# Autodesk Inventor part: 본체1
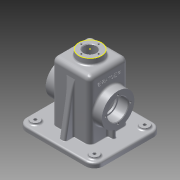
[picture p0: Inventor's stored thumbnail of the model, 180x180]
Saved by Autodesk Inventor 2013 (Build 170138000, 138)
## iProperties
Created: 2016-01
Part Number: 본체1
Material: 알루미늄 6061
Document SubType Name: Modeling
Designer: Administrator
Density: 2.71 g/cm^3
Mass: 805.054 g
Surface Area: 908.341 cm^2
Volume: 297.068 cm^3
Author: Administrator
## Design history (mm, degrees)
sketch "스케치1"
  geometry: 1 further point
sketch "스케치2"
  geometry: L1 (-32.5, 32.5)-(32.5, 32.5); L2 (32.5, 32.5)-(32.5, -32.5); L3 (32.5, -32.5)-(-32.5, -32.5); L4 (-32.5, -32.5)-(-32.5, 32.5); 3 further points
  constraints: 8 end point, 2 midpoint, 2 parallel, 1 horizontal, 1 horizontal alignment, 1 perpendicular, 1 vertical alignment
  dimensions: "d0" = 65 distance of L1.start L1.end; "d2" = 65 distance of L1.end L2.end
extrude "돌출1" new body sketch "스케치2" distance "d3" = 110; taper "d4" = 0 deg
fillet "모깎기1" dims "d5" = 8
fillet "모깎기2" dims "d6" = 8
feature "쉘1" dims "d7" = 5
sketch "스케치3"
  geometry: C1 r 20 at (0, 0); 1 further point
  constraints: 1 centre point, 1 coincident
  dimensions: "d8" = 40 diameter of C1
extrude "돌출2" join sketch "스케치3" distance "d9" = 10; taper "d10" = 0 deg
feature "면 기울기1" dims angle "d11" = 5 deg
sketch "스케치4"
  geometry: C1 r 19.125 at (0, 0) reference
hole "구멍1" diameter "d14" = 21; stored, may be unused: countersink angle "d18" = 90 deg, drill point angle "d20" = 0 deg; dims "d12" = 10, "d13" = 10, "d15" = 6, "d16" = 4, "d17" = 2, "d19" = 8
sketch "스케치5"
  geometry: L1 (0, 0)-(0, 49) reference; C1 r 27.5 at (55, 24.5); 3 further points
  constraints: 1 centre point, 1 coincident, 1 horizontal alignment, 1 midpoint
  dimensions: "d21" = 55 distance of point (0, 24.5) point (55, 24.5); "d22" = 55 diameter of C1
extrude "돌출3" join sketch "스케치5" distance "d23" = 15; taper "d25" = 0 deg; dims "d24" = 5, "d26" = 0
hole "구멍2" diameter "d29" = 30; stored, may be unused: countersink angle "d33" = 90 deg, drill point angle "d35" = 0 deg; dims "d27" = 10, "d28" = 10, "d30" = 6, "d31" = 35, "d32" = 17, "d34" = 8
sketch "스케치6"
  geometry: L1 (24.5, 32.5)-(-24.5, 32.5) reference; L2 (-32.5, 24.5)-(-32.5, -24.5) reference; L3 (-24.5, -32.5)-(24.5, -32.5) reference; L4 (32.5, -24.5)-(32.5, 24.5) reference; L5 (-65, -57.5)-(65, -57.5); L6 (65, -57.5)-(65, 57.5); L7 (65, 57.5)-(-65, 57.5); L8 (-65, 57.5)-(-65, -57.5); A1 r 8 centre (24.5, 24.5) between (32.5, 24.5) and (24.5, 32.5) reference; A2 r 8 centre (-24.5, 24.5) between (-24.5, 32.5) and (-32.5, 24.5) reference; A3 r 8 centre (-24.5, -24.5) between (-32.5, -24.5) and (-24.5, -32.5) reference; A4 r 8 centre (24.5, -24.5) between (24.5, -32.5) and (32.5, -24.5) reference; 3 further points
  constraints: 8 end point, 2 midpoint, 2 parallel, 1 horizontal, 1 horizontal alignment, 1 perpendicular, 1 vertical alignment
  dimensions: "d36" = 115 distance of L7.end L5.start; "d38" = 130 distance of L6.end L7.end
extrude "돌출4" join sketch "스케치6" distance "d39" = 10; taper "d40" = 0 deg
fillet "모깎기3" dims "d41" = 15
sketch "스케치7"
  geometry: L1 (50, 57.5)-(-50, 57.5) reference; L2 (-65, 42.5)-(-65, -42.5) reference; L3 (-50, -57.5)-(50, -57.5) reference; L4 (65, -42.5)-(65, 42.5) reference; L5 (50, -52.5)-(-50, -52.5); L6 (-60, -42.5)-(-60, 42.5); L7 (-50, 52.5)-(50, 52.5); L8 (60, 42.5)-(60, -42.5); A1 r 15 centre (50, 42.5) between (65, 42.5) and (50, 57.5) reference; A2 r 15 centre (-50, 42.5) between (-50, 57.5) and (-65, 42.5) reference; A3 r 15 centre (-50, -42.5) between (-65, -42.5) and (-50, -57.5) reference; A4 r 15 centre (50, -42.5) between (50, -57.5) and (65, -42.5) reference; A5 r 10 centre (-50, -42.5) between (-60, -42.5) and (-50, -52.5); A6 r 10 centre (-50, 42.5) between (-50, 52.5) and (-60, 42.5); A7 r 10 centre (50, 42.5) between (60, 42.5) and (50, 52.5); A8 r 10 centre (50, -42.5) between (50, -52.5) and (60, -42.5); 1 further point
  constraints: 8 end point, 8 point on circle, 4 centre point, 7 other
  dimensions: "d42" = 5 distance between parallel lines of L3 L5
extrude "돌출5" cut sketch "스케치7" distance "d43" = 2; taper "d44" = 0 deg
sketch "스케치8"
  geometry: C1 r 17.5 at (0, 0) reference; 2 further points
  constraints: 1 horizontal alignment
  dimensions: "d45" = 21 distance of point (21, 0) C1.centre
hole "구멍3" sketch "스케치8" at (21, 0) diameter "d46" = 3.242; stored, may be unused: countersink angle "d50" = 90 deg, drill point angle "d52" = 118 deg; dims "d47" = 8, "d48" = 35, "d49" = 17, "d51" = 10
sketch "스케치9"
  geometry: C1 r 10.5 at (0, 0) reference; 1 further point
  constraints: 1 horizontal alignment
  dimensions: "d56" = 14.5 distance of C1.centre point (-14.5, 0)
hole "구멍4" sketch "스케치9" at (-14.5, 0) diameter "d57" = 2.459; stored, may be unused: countersink angle "d61" = 90 deg, drill point angle "d63" = 118 deg; dims "d58" = 7, "d59" = 35, "d60" = 17, "d62" = 9
sketch "스케치10"
  geometry: C1 r 7.5 at (-50, -42.5); C2 r 7.5 at (-50, 42.5); C3 r 7.5 at (50, 42.5); C4 r 7.5 at (50, -42.5); A1 r 15 centre (-50, 42.5) between (-50, 57.5) and (-65, 42.5) reference; A2 r 15 centre (-50, -42.5) between (-65, -42.5) and (-50, -57.5) reference; A3 r 15 centre (50, -42.5) between (50, -57.5) and (65, -42.5) reference; A4 r 15 centre (50, 42.5) between (65, 42.5) and (50, 57.5) reference; 1 further point
  constraints: 4 centre point, 4 coincident
  dimensions: "d67" = 15 diameter of C1; "d68" = 15 diameter of C2; "d69" = 15 diameter of C3; "d70" = 15 diameter of C4
extrude "돌출6" join sketch "스케치10" distance "d71" = 3; taper "d72" = 0 deg
hole "구멍5" diameter "d75" = 5; stored, may be unused: countersink angle "d79" = 90 deg, drill point angle "d81" = 118 deg; dims "d73" = 10, "d74" = 10, "d76" = 7, "d77" = 35, "d78" = 17, "d80" = 9
sketch "스케치11"
  geometry: L1 (-47.5, 37.5)-(-30.5, 37.5) reference; L2 (-30.5, 37.5)-(-30.5, 40) reference; L3 (-30.5, 40)-(-27.5, 40) reference; L4 (-27.5, 40)-(-27.5, 0) reference; L5 (-27.5, 0)-(-60, 0) reference; L6 (-60, 0)-(-60, 2) reference; L7 (-60, 2)-(-65, 2) reference; L8 (-65, 2)-(-65, 10) reference; L9 (-65, 10)-(-32.5, 10) reference; L10 (-32.5, 10)-(-32.5, 27.5) reference; L11 (-32.5, 27.5)-(-47.5, 27.5) reference; L12 (-47.5, 27.5)-(-47.5, 32.379) reference; L13 (-47.5, 32.379)-(-37.5, 32.379) reference; L14 (-37.5, 32.379)-(-36.526, 34) reference; L15 (-36.526, 34)-(-37.5, 35.621) reference; L16 (-37.5, 35.621)-(-47.5, 35.621) reference; L17 (-47.5, 35.621)-(-47.5, 37.5) reference; L18 (47.5, 27.5)-(32.5, 27.5) reference; L19 (32.5, 27.5)-(32.5, 10) reference; L20 (32.5, 10)-(65, 10) reference; L21 (65, 10)-(65, 2) reference; L22 (65, 2)-(60, 2) reference; L23 (60, 2)-(60, 0) reference; L24 (60, 0)-(27.5, 0) reference; L25 (27.5, 0)-(27.5, 40) reference; L26 (30.5, 40)-(30.5, 37.5) reference; L27 (30.5, 37.5)-(47.5, 37.5) reference; L28 (47.5, 37.5)-(47.5, 35.621) reference; L29 (47.5, 35.621)-(37.5, 35.621) reference; L30 (37.5, 35.621)-(36.526, 34) reference; L31 (36.526, 34)-(37.5, 32.379) reference; L32 (37.5, 32.379)-(47.5, 32.379) reference; L33 (47.5, 32.379)-(47.5, 27.5) reference; L34 (19.125, 120)-(20, 110) reference; L35 (20, 110)-(24.5, 110) reference; L36 (32.5, 102)-(32.5, 82.5) reference; L37 (32.5, 82.5)-(47.5, 82.5) reference; L38 (47.5, 82.5)-(47.5, 77.621) reference; L39 (47.5, 77.621)-(37.5, 77.621) reference; L40 (37.5, 77.621)-(36.526, 76) reference; L41 (36.526, 76)-(37.5, 74.379) reference; L42 (37.5, 74.379)-(47.5, 74.379) reference; L43 (47.5, 74.379)-(47.5, 72.5) reference; L44 (47.5, 72.5)-(30.5, 72.5) reference; L45 (30.5, 72.5)-(30.5, 70) reference; L46 (27.5, 70)-(27.5, 102) reference; L47 (24.5, 105)-(10.5, 105) reference; L48 (10.5, 105)-(10.5, 120) reference; L49 (10.5, 120)-(13.271, 120) reference; L50 (13.271, 120)-(13.271, 111) reference; L51 (13.271, 111)-(14.5, 110.261) reference; L52 (14.5, 110.261)-(15.73, 111) reference; L53 (15.73, 111)-(15.73, 120) reference; L54 (15.73, 120)-(19.125, 120) reference; L55 (-20, 110)-(-19.125, 120) reference; L56 (-19.125, 120)-(-15.73, 120) reference; L57 (-15.73, 120)-(-15.73, 111) reference; L58 (-15.73, 111)-(-14.5, 110.261) reference; L59 (-14.5, 110.261)-(-13.271, 111) reference; L60 (-13.271, 111)-(-13.271, 120) reference; L61 (-13.271, 120)-(-10.5, 120) reference; L62 (-10.5, 120)-(-10.5, 105) reference; L63 (-10.5, 105)-(-24.5, 105) reference; L64 (-27.5, 102)-(-27.5, 70) reference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; A1 r 8 centre (24.5, 102) between (32.5, 102) and (24.5, 110) reference; A2 r 3 centre (24.5, 102) between (27.5, 102) and (24.5, 105) reference; A3 r 3 centre (-24.5, 102) between (-24.5, 105) and (-27.5, 102) reference; A4 r 8 centre (-24.5, 102) between (-24.5, 110) and (-32.5, 102) reference; 1 further point
  constraints: 2 end point, 1 point on line, 1 vertical
  dimensions: "d82" = 15 distance between parallel lines of L77 L25
feature "리브1" sketch "스케치11" dims "d83" = 1, "d84" = 6, "d85" = 0, "d86" = 0, "d87" = 1, "d88" = 1
sketch "스케치12"
  geometry: L1 (13.271, 111)-(14.5, 110.261) reference; L2 (14.5, 110.261)-(15.73, 111) reference; L3 (15.73, 111)-(15.73, 120) reference; L4 (15.73, 120)-(19.125, 120) reference; L5 (19.125, 120)-(20, 110) reference; L6 (20, 110)-(24.5, 110) reference; L7 (32.5, 102)-(32.5, 10) reference; L8 (32.5, 10)-(57.5, 10) reference; L9 (57.5, 10)-(57.5, 2) reference; L10 (57.5, 2)-(52.5, 2) reference; L11 (52.5, 2)-(52.5, 0) reference; L12 (52.5, 0)-(27.5, 0) reference; L13 (27.5, 0)-(27.5, 102) reference; L14 (24.5, 105)-(10.5, 105) reference; L15 (10.5, 105)-(10.5, 120) reference; L16 (10.5, 120)-(13.271, 120) reference; L17 (13.271, 120)-(13.271, 111) reference; L18 (-24.5, 110)-(-20, 110) reference; L19 (-20, 110)-(-19.125, 120) reference; L20 (-19.125, 120)-(-15.73, 120) reference; L21 (-15.73, 120)-(-15.73, 111) reference; L22 (-15.73, 111)-(-14.5, 110.261) reference; L23 (-14.5, 110.261)-(-13.271, 111) reference; L24 (-13.271, 111)-(-13.271, 120) reference; L25 (-13.271, 120)-(-10.5, 120) reference; L26 (-10.5, 120)-(-10.5, 105) reference; L27 (-10.5, 105)-(-24.5, 105) reference; L28 (-27.5, 102)-(-27.5, 0) reference; L29 (-27.5, 0)-(-52.5, 0) reference; L30 (-52.5, 0)-(-52.5, 2) reference; L31 (-52.5, 2)-(-57.5, 2) reference; L32 (-57.5, 2)-(-57.5, 10) reference; L33 (-57.5, 10)-(-32.5, 10) reference; L34 (-32.5, 10)-(-32.5, 102) reference; L35 (-47.5, 10)-(-32.5, 95.069); A1 r 8 centre (24.5, 102) between (32.5, 102) and (24.5, 110) reference; A2 r 3 centre (24.5, 102) between (27.5, 102) and (24.5, 105) reference; A3 r 8 centre (-24.5, 102) between (-24.5, 110) and (-32.5, 102) reference; A4 r 3 centre (-24.5, 102) between (-24.5, 105) and (-27.5, 102) reference; 1 further point
  constraints: 2 end point, 2 point on line, 1 horizontal alignment
  dimensions: "d89" = 10 distance of L35.start L32.end; "d90" = 10 deg angle of L35 L32
feature "리브2" sketch "스케치12" dims "d91" = 1, "d92" = 10, "d93" = 0, "d94" = 0, "d95" = 1, "d96" = 1
fillet "모깎기4" dims "d97" = 0.3
node "작업 평면1"
sketch "스케치13"
  geometry: L1 (-18, 43.625)-(-18, 5.375) reference; L2 (0, -8)-(92, -8) reference; 2 further points
  constraints: 1 other
  dimensions: "d99" = 27 distance from line of point (9, 24.5) L1; "d100" = 32.5 distance from line of point (9, 24.5) L2
feature "엠보싱1" sketch "스케치13" dims "d101" = 0.5, "d102" = 0
chamfer "모따기1" distance "d103" = 1; stored, may be unused: second distance "d104" = 2, angle "d105" = 45 deg
chamfer "모따기2" distance "d106" = 1; stored, may be unused: second distance "d107" = 2, angle "d108" = 45 deg
chamfer "모따기3" distance "d109" = 1; stored, may be unused: second distance "d110" = 2, angle "d111" = 45 deg
fillet "모깎기5" dims "d112" = 3
fillet "모깎기6" dims "d113" = 3
fillet "모깎기7" dims "d114" = 3
fillet "모깎기8" dims "d115" = 3
fillet "모깎기9" dims "d116" = 3
fillet "모깎기10" dims "d117" = 3
fillet "모깎기11" dims "d118" = 3
fillet "모깎기12" dims "d119" = 1
node "솔리드1"
mirror "대칭1"
pattern_circular "원형 패턴1" dims angle "d54" = 360 deg
mirror "대칭2"
pattern_circular "원형 패턴2" dims angle "d65" = 360 deg
mirror "대칭3"
mirror "대칭4"
mirror "대칭5"
mirror "대칭6"
node "절단 모서리 투영1"
node "절단 모서리 투영2"
other parameters: "d98" = 11.25
